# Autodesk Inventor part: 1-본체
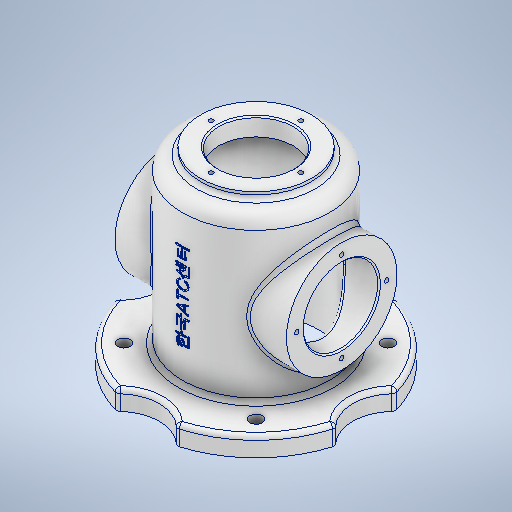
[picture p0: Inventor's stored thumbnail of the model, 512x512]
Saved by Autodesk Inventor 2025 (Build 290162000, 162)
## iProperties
Created: 2026-07
Part Number: 1-본체
Material: 알루미늄 6061
Document SubType Name: Modeling
Designer: KDI
Density: 2.7 g/cm^3
Appearance: 알루미늄 - 평지
Mass: 1502.39 g
Surface Area: 1246.39 cm^2
Volume: 556.44 cm^3
Author: KDI
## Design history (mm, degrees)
sketch "스케치1" dims "d0" = 164
  geometry: L1 (0, 0)-(0, -82); L2 (0, 0)-(-47.73, -47.73); L3 (0, 0)-(-67.5, 0); C1 r 30 at (100, 0); C2 r 30 at (0, 100); C3 r 30 at (-100, 0); C4 r 30 at (0, -100); C5 r 4.5 at (-47.73, -47.73); C6 r 4.5 at (-47.73, 47.73); C7 r 4.5 at (47.73, -47.73); C8 r 4.5 at (47.73, 47.73); A1 r 67.5 centre (0, 0) between (-47.73, -47.73) and (-67.5, 0); 10 further points
  constraints: 9 centre point, 6 end point, 3 coincident, 3 symmetric about line, 2 point on circle, 1 horizontal, 1 horizontal alignment, 1 vertical, 15 other
  dimensions: "d1" = 60 diameter of C1; "d2" = 100 distance of point (0, 0) C1.centre; "d5" = 360 deg dimension on point (0, 0) C1.centre (derived); "d7" = 135 diameter of A1; "d8" = 45 deg angle of L1 L2; "d9" = 9 diameter of C5
extrude "돌출1" new body sketch "스케치1" distance "d10" = 14; taper "d11" = 0 deg
sketch "스케치2"
  geometry: C1 r 53 at (0, 0); 1 further point
  constraints: 1 centre point, 1 coincident
  dimensions: "d12" = 106 diameter of C1
extrude "돌출2" join sketch "스케치2" distance "d13" = 132; taper "d14" = 0 deg
sketch "스케치3"
  geometry: C1 r 53 at (0, 0) reference; C2 r 40 at (0, 0); 1 further point
  constraints: 1 centre point, 1 coincident
  dimensions: "d15" = 80 diameter of C2
extrude "돌출3" join sketch "스케치3" distance "d16" = 5; taper "d17" = 0 deg
sketch "스케치4"
  geometry: C1 r 40 at (68, 0); 1 further point
  constraints: 1 centre point, 1 horizontal alignment
  dimensions: "d18" = 80 diameter of C1; "d19" = 68 distance of point (0, 0) C1.centre
extrude "돌출4" join sketch "스케치4" stored distance "d20" = 124; taper "d21" = 0 deg
sketch "스케치5"
  geometry: C1 r 45 at (0, 0); 1 further point
  constraints: 1 centre point, 1 coincident
  dimensions: "d22" = 90 diameter of C1
extrude "돌출5" cut sketch "스케치5" distance "d23" = 124; taper "d24" = 0 deg
sketch "스케치6"
  geometry: C1 r 27 at (0, 0); 1 further point
  constraints: 1 centre point, 1 coincident
  dimensions: "d25" = 54 diameter of C1
extrude "돌출6" cut sketch "스케치6" distance "d26" = 124; taper "d27" = 0 deg
sketch "스케치7"
  geometry: A1 r 32.5 centre (0, 0) between (0, 32.5) and (-32.5, 0); 3 further points
  constraints: 4 point on circle, 2 horizontal alignment, 2 vertical alignment, 1 centre point, 1 coincident
  dimensions: "d28" = 65 diameter of A1
hole "구멍1" sketch "스케치7" at (0, 32.5), (-32.5, 0), (0, -32.5), (32.5, 0) diameter "d29" = 3.242; stored, may be unused: countersink angle "d33" = 90 deg, drill point angle "d35" = 118 deg; dims "d30" = 8, "d31" = 4, "d32" = 2, "d34" = 10
sketch "스케치8"
  geometry: L1 (-21.541, -68)-(21.541, -68) reference; C1 r 27 at (0, 0); 2 further points
  constraints: 1 centre point, 1 midpoint, 1 vertical alignment
  dimensions: "d36" = 54 diameter of C1; "d37" = 68 distance from line of L1 C1.centre
extrude "돌출7" cut sketch "스케치8" extent not by distance; stored distance "d38" = 0; taper "d39" = 0 deg
sketch "스케치9"
  geometry: L1 (-21.541, -68)-(21.541, -68) reference; A1 r 32.5 centre (0, 0) between (0, 32.5) and (-32.5, 0); 5 further points
  constraints: 4 point on circle, 3 vertical alignment, 2 horizontal alignment, 2 midpoint, 1 centre point
  dimensions: "d40" = 65 diameter of A1; "d41" = 68 distance of point (0, -68) A1.centre
hole "구멍2" sketch "스케치9" at (0, 32.5), (-32.5, 0), (0, -32.5), (32.5, 0) diameter "d42" = 3.242; stored, may be unused: countersink angle "d46" = 90 deg, drill point angle "d48" = 118 deg; dims "d43" = 8, "d44" = 4, "d45" = 2, "d47" = 10
sketch "스케치10"
  geometry: L1 (-21.541, 0)-(21.541, 0) reference; 4 further points
  constraints: 2 midpoint, 1 vertical alignment, 1 other
  dimensions: "d49" = 70 distance of point (0, 0) point (0, 70)
feature "엠보싱1" sketch "스케치10" dims "d50" = 0.5, "d51" = 0
fillet "모깎기1" dims "d52" = 10
fillet "모깎기2" dims "d53" = 3
fillet "모깎기3" dims "d54" = 3
fillet "모깎기4" dims "d55" = 3
chamfer "모따기1" distance "d56" = 1; stored, may be unused: second distance "d57" = 2, angle "d58" = 45 deg
node "솔리드1"
mirror "미러1"
node "스케치 - 원형 패턴1" dims "d5" = 360 deg (derived)
feature "A9D066F2-1C7D-4E18-AEED-F7BC21143FA4" dims "d42" = 3.242, "d43" = 8, "d44" = 4, "d45" = 2, "d46" = 90 deg, "d47" = 10, "d48" = 118 deg
